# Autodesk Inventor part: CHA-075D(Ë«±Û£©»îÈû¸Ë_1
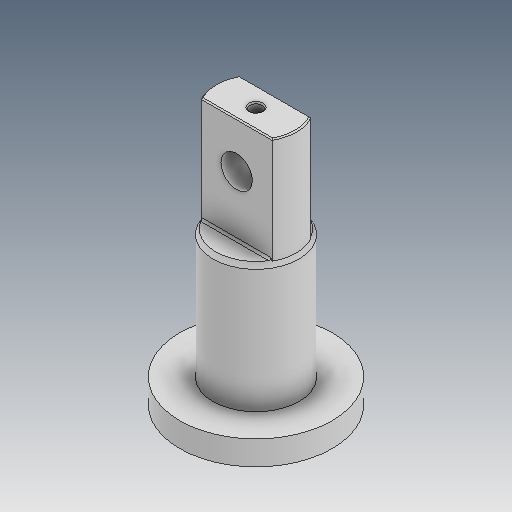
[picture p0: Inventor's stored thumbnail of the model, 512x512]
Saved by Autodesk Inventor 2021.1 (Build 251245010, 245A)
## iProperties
Created: 2019-12
Part Number: CHA-075D(Ë«±Û£©»îÈû¸Ë_1
Material: Ogólny
Document SubType Name: Modeling
Designer: user
Density: 1 g/cm^3
Appearance: Domyślna
Author: user
Revision Number: ÈÎºÎ
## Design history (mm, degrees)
feature "ÊäÈë1"
node "Bryła1"
